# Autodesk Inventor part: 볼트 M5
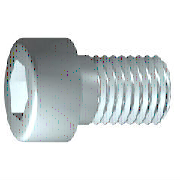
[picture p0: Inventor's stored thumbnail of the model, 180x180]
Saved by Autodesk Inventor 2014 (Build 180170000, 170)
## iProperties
IsCustomPart: 1
Created: 2012-02
Part Number: 볼트 M5
Material: 강철, 연강
Description: 6각머리 태핑 나사
Document SubType Name: Modeling
Standard: KS B 1003
Designer: mduedu
Standards Organization: KS
Language: ko-KR
Size Designation: M 5 x 16
Categories: <MemberInstance><Categories><Category DisplayName="조임쇠" InternalName="e4da775c-781d-43d5-af7c-5136215cf5a6" Mnemonic="FSTN"><Category DisplayName="볼트" InternalN
Density: 1 g/cm^3
Appearance: 강철
Author: mduedu
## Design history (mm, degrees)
sketch "스케치1"
  geometry: L1 (-1.167, 0)-(16, 0); L2 (16, 0)-(16, 2.5); L3 (16, 2.5)-(2, 2.5); L4 (2, 2.5)-(1.509, 2.5); L5 (1.509, 2.5)-(0, 2.5); L6 (0, 2.5)-(0, 4.25); L7 (0, 4.25)-(-5, 4.25); L8 (-5, 4.25)-(-5, 2.309); L9 (-5, 2.309)-(-2.5, 2.309); L10 (-2.5, 2.309)-(-1.167, 0); L11 (-9.2, 0)-(20.2, 0) reference; L12 (0, -0.85)-(0, 5.1) reference; L13 (2, 2.5)-(0, 2.5)
  constraints: 22 end point, 6 parallel, 2 collinear, 2 perpendicular, 1 horizontal, 1 point on line
  dimensions: "d1" = 14 distance from line of L3.end L2 (= GEL); "d2" = 0.49086 distance of L4.end L3.end (computed from GAL); "d3" = 5 distance between parallel lines of L8 L6 (= KOH); "d4" = 2.5 distance of L8.end L9.end (= INTI); "d5" = 60 deg angle of L10 L1; "d6" = 5 diameter of L3 L1 (= GD); "d7" = 5 diameter of L5 L1 (= BDM); "d8" = 4.6188 diameter of L9 L1 (= 1.1547 x SW); "d9" = 8.5 diameter of L7 L1 (= KOD); "d26" = 16 distance between parallel lines of L12 L2 (= NLG)
revolve "본체" sketch "스케치1" stored, may be unused: angle "d10" = 90 deg
sketch "스케치2"
  geometry: L1 (0, -5.95)-(0, 5.95) reference; L2 (-5.95, 0)-(5.95, 0) reference; L3 (2.309, 0)-(1.155, -2); L4 (1.155, -2)-(-1.155, -2); L5 (-1.155, -2)-(-2.309, 0); L6 (-2.309, 0)-(-1.155, 2); L7 (-1.155, 2)-(1.155, 2); L8 (1.155, 2)-(2.309, 0); 2 further points
  constraints: 12 end point, 1 coincident, 1 horizontal alignment, 1 point on line, 12 other
extrude "슬롯" join sketch "스케치2" stored distance "d11" = 10; taper "d12" = 0 deg
workplane "Work Plane1"
fillet "Fillet2" dims "d30" = 0.1 (= R)
body "Solid1"
fillet "모깎기1" dims "d17" = 0.5 (= RR)
feature "스레드" dims "d13" = 14 (= GEL), "d14" = 0
chamfer "모따기1" distance "d15" = 0.49076 (= -0.5 x SPD + 0.5 x GD); stored, may be unused: second distance "d16" = 0.49076 (= GUL), angle "d27" = 45 deg
other parameters: "GD" = 5 (= NND) [user parameter; used in 2 equation terms], "NLG" = 16 [user parameter; used in 1 equation term], "GEL" = 14 [user parameter; used in 2 equation terms], "KOD" = 8.5 [user parameter; used in 1 equation term], "KOH" = 5 [user parameter; used in 1 equation term], "INTI" = 2.5 [user parameter; used in 1 equation term], "GAL" = 0.49076 (= 0.61345 x PTC) [user parameter; used in 1 equation term], "GUL" = 0.49076 (= 0.61345 x PTC) [user parameter; used in 1 equation term], "BDM" = 5 (= NND) [user parameter; used in 1 equation term], "SW" = 4 [user parameter; used in 2 equation terms], "RR" = 0.5 [user parameter; used in 1 equation term], "SPD" = 4.01848 (= NND - 1.2269 x PTC) [user parameter; used in 1 equation term], "d19" = 0, "d28" = 0, "d29" = 0, "R" = 0.1 [user parameter; used in 1 equation term], "PHH" = 0.2 [user parameter], "GD1" = 4.01848 (= THREADDIA - 1.2269 x PTC) [user parameter], "THREADDIA" = 5 [user parameter; used in 1 equation term], "FAWI" = 45 deg [user parameter], "TPU" = 12.5 (computed from PTC) [user parameter], "PTC" = 0.8 [user parameter; used in 5 equation terms], "NND" = 5 [user parameter; used in 3 equation terms], "TOA" = 30 deg [user parameter], "E0" = 4.62 (= 1.155 x SW) [user parameter]
